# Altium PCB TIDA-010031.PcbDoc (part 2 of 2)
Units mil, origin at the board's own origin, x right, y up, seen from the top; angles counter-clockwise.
Board outline 1982.49 x 1977.57 mil, 2 copper layers (Top Layer, Bottom Layer), stack 62 mil thick; 85 components, 79 nets, 332 pads, 189 vias.
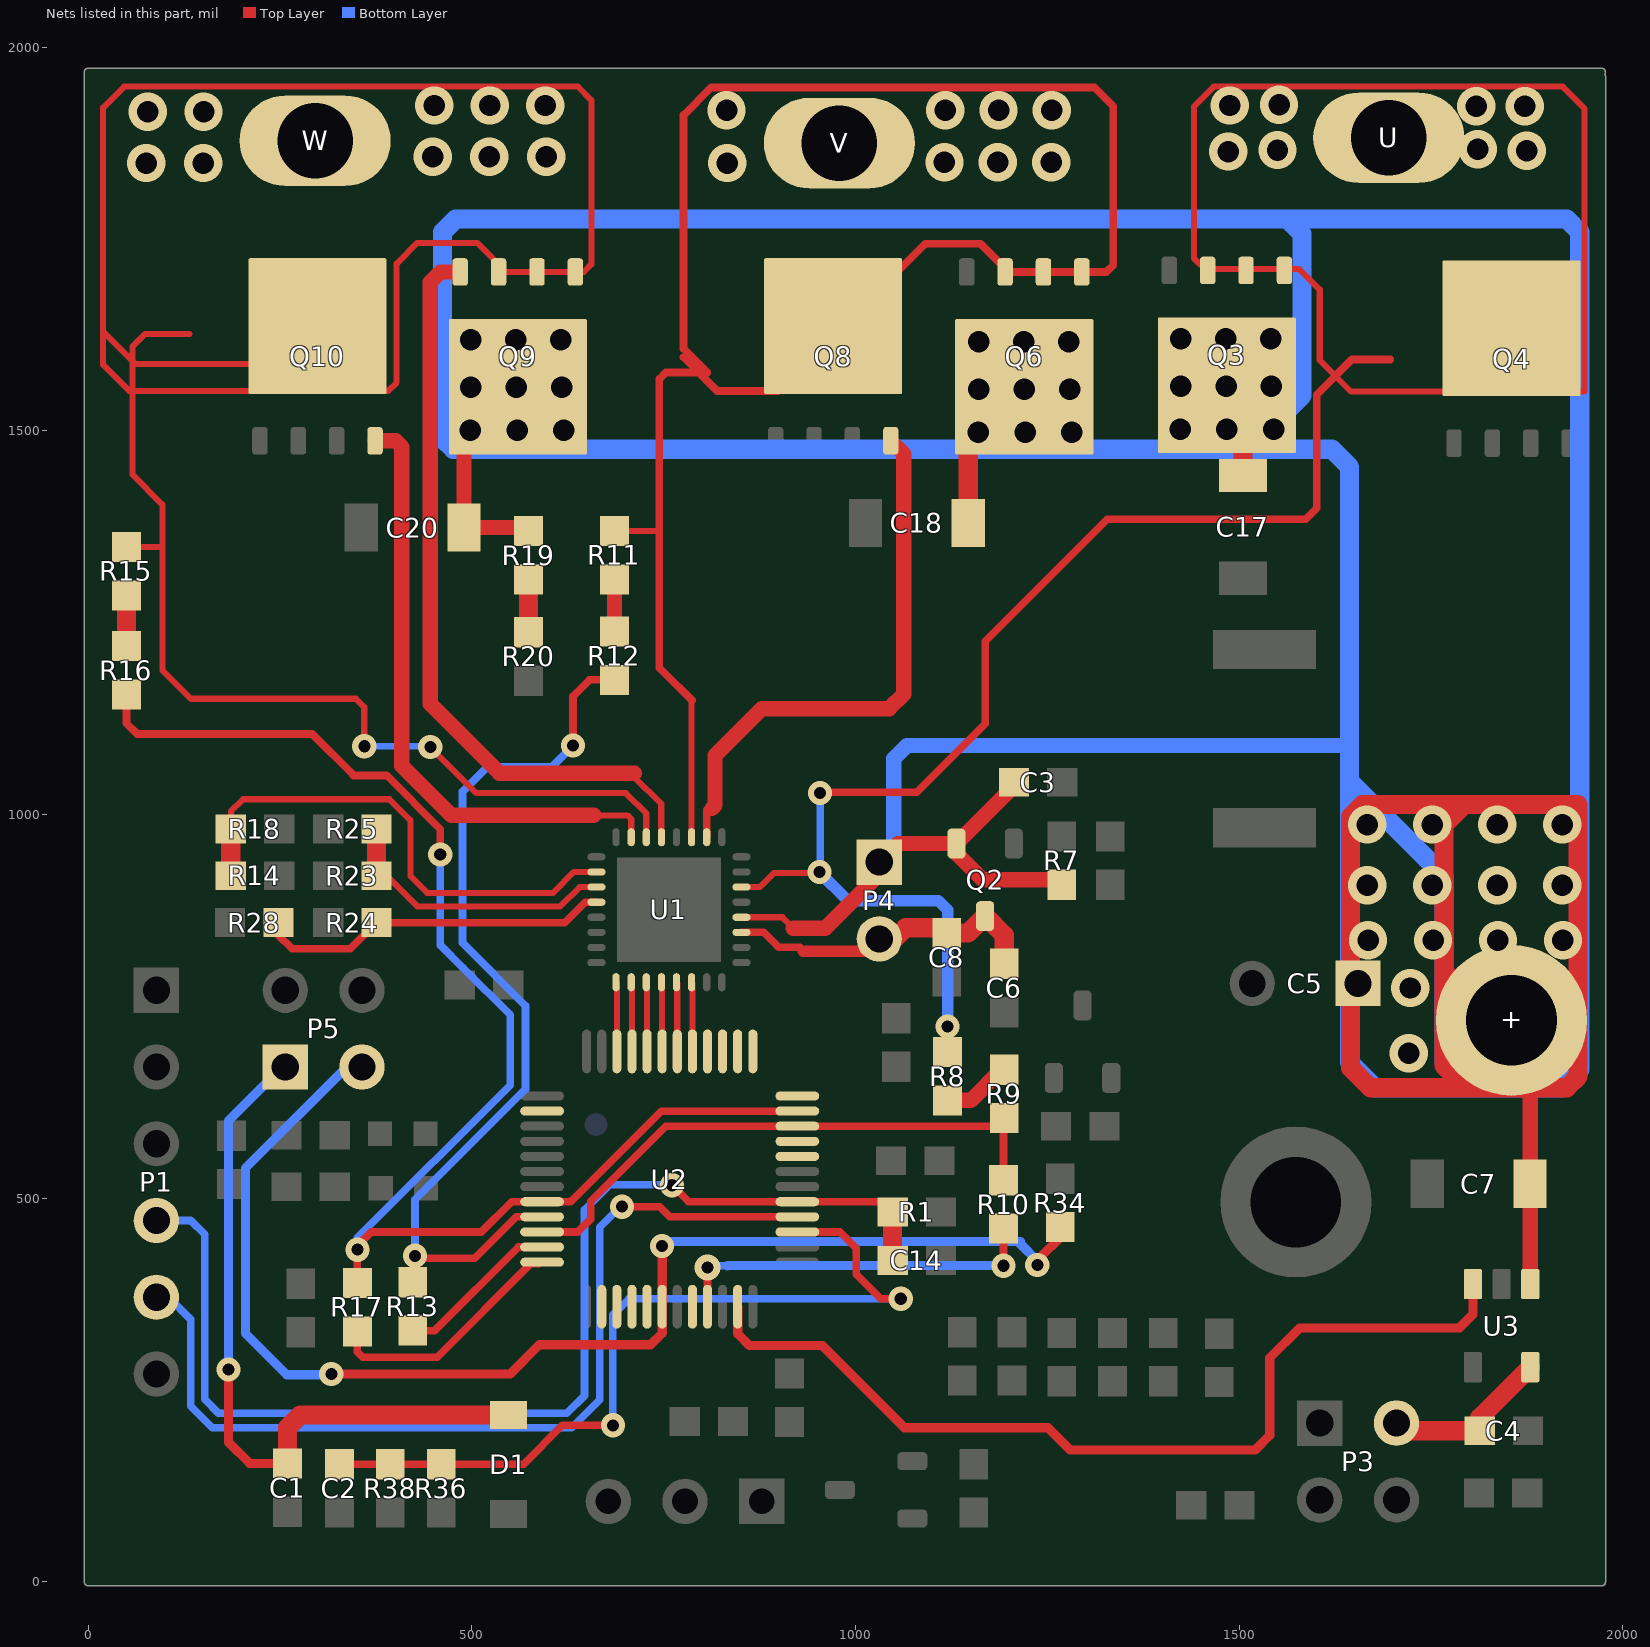
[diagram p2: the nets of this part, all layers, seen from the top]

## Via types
v1: diameter 50, hole 28, Top Layer to Bottom Layer, 132 vias
v2: diameter 31.5, hole 15.75, Top Layer to Bottom Layer, 51 vias
v3: diameter 19.68, hole 7.87, Top Layer to Bottom Layer, 5 vias
v4: diameter 34, hole 16, Top Layer to Bottom Layer, 1 vias

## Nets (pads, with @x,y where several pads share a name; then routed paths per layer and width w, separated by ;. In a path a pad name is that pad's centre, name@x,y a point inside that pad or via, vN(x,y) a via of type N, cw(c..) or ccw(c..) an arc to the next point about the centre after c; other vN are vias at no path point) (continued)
NetQ8_4: Q8.4 U1.10 | length 722.5
  Top Layer w10: U1.10@806.21,970.49 806.21,986.21 806.21,1006.21
  Top Layer w20: 813,1008 817,1012 817,1077 878,1138 1044,1138 1063,1157 1063,1469.96 Q8.4@1046,1486.96
NetQ9_4: Q9.4 U1.13 | length 990.7
  Top Layer w8: 712,1048.93 747,1013.93 747,1011 747,970.65 U1.13@747.16,970.49
  Top Layer w20: Q9.4@485,1707.04 459.04,1707.04 446,1694 446,1293 446,1144 536,1054 712,1054
NetQ10_4: Q10.4 U1.15 | length 839
  Top Layer w8: 625,999 703,999 707.79,994.21 U1.15@707.79,970.49
  Top Layer w20: Q10.4@374,1486.96 401.04,1486.96 409,1479 409,1063.53 473.53,999 625,999 659,999
NetR8_2: R8.2 R9.1 | length 90.6
  Top Layer w20: R8.2@1120,627.5 1150.33,627.5 1190.32,667.5 R9.1@1194,667.5
NetR11_2: R11.2 R12.1 | length 68
  Top Layer w20: R12.1@686,1238.5 R11.2@686,1306.5
NetR14_1: R14.1 R18.2 U1.18 | length 732.2
  Top Layer w8: R14.1@186.06,920.3 186.06,1004.05 202,1020 392.7,1020 420,992.7 420,920 442,898 606,898 633.21,925.21 U1.18@662.51,925.21
  Top Layer w25: R14.1@186.06,920.3 R18.2@186.06,981.3
NetR15_2: R15.2 R16.1 | length 66
  Top Layer w25: R16.1@50,1219.5 R15.2@50,1285.5
NetR19_2: R19.2 R20.1 | length 69
  Top Layer w25: R20.1@574,1237.5 R19.2@574,1306.5
NetR23_1: R23.1 R25.2 U1.19 | length 374.7
  Top Layer w8: R23.1@376.05,920.3 389.23,920.3 429.53,880 615,880 640.53,905.53 U1.19@662.51,905.53
  Top Layer w25: R23.1@376.05,920.3 R25.2@376.05,981.3
NetR24_1: R24.1 R28.2 U1.20 | length 463.7
  Top Layer w10: R28.2@248.05,859.3 248.05,842.95 266,825 341.75,825 R24.1@376.05,859.3 376.35,859 621,859 647.84,885.84 U1.20@662.51,885.84
ON_OFF: C1.1 D1.1 P5.1 | length 951.7
  Top Layer w12: v2(183,277) 183,182 210.5,154.5 C1.1@260,154.5
  Top Layer w25: C1.1@260,154.5 260,201 276.47,217.47 D1.1@548,217.47
  Bottom Layer w12: v2(183,277) 183,601 253,671 P5.1@257,671
P1.0: C2.1 R36.2 R38.2 U2.3 | length 1095.3
  Top Layer w10: C2.1@327.65,153.5 567.5,153.5 618.12,204.12 v2(683.88,204.12) ; U2.3@924.34,456.1 979.65,456.1 1001,434.75 1001,401 1033,369 v2(1059,369)
  Bottom Layer w10: v2(683.88,204.12) 683.88,347.88 705,369 v2(1059,369)
P1.4: R9.2 R10.1 U2.10 U2.34 | length 740
  Top Layer w10: U2.34@591.66,456.1 638.1,456.1 655,473 655,496 752.9,593.9 U2.10@924.34,593.9 1189.1,593.9 1193,590 R10.1@1193,523.5
P1.5: R12.2 R13.1 U2.33 | length 1238.7
  Top Layer w10: R13.1@423,390.5 v2@423,422 ; v2@429,428 v2@434,423 ; v2@433.5,432.5 v2@423,422 ; U2.33@591.66,475.79 557.79,475.79 504,422 v2@423,422 ; v2(632,1090) 632,1154 653.5,1175.5 R12.2@686,1175.5
  Bottom Layer w10: v2(426,425) 426,498 570,642 570,751 488,833 488,1030 520,1062 604,1062 v2(632,1090)
P1.6: R16.2 R17.1 U2.11 U2.32 | length 1884.7
  Top Layer w10: R16.2@50,1156.5 50,1119 64,1105 292,1105 346,1051 389,1051 459,981 v2(459,948) ; R17.1@351,389.5 351,438 369,456 512.46,456 551.93,495.47 U2.32@591.66,495.47 629.02,495.47 747.13,613.58 U2.11@924.34,613.58
  Bottom Layer w10: v2(351,433) 351,448.46 550,647.46 550,739 489,800 ; v2(459,948) 459,830 489,800 ; 502,787 489,800
P2.6: U2.9
P2.7: U2.8
P3.0: U2.47 U3.3 | length 1227.8
  Top Layer w12: U2.47@846.58,358.66 846.58,323.42 862,308 957,308 1064,201 1251,201 1280,172 1521,172 1540,191 1540,292 1579,331 1787,331 1804.6,348.6 U3.3@1804.6,388.13
P3.2: R10.2 U2.45 | length 493.9
  Top Layer w10: U2.45@807.21,358.66 v4(807.21,409.79) v4@807.21,411.79 ; v2(1193,412) R10.2@1193,460.5
  Bottom Layer w10: v4(807.21,409.79) 809.43,412 833,412
  Bottom Layer w12: 833,412 1193,412.25 v2@1193.25,412.25 ; v2@1189.25,408.25 v2(1193,412)
P3.3: U2.44
P3.4: U2.38
P3.6: R17.2 U2.36 | length 316.3
  Top Layer w10: R17.2@351,326.5 351,300 358,293 455,293 577,415 U2.36@587.32,415
P3.7: R13.2 U2.35 | length 213.8
  Top Layer w10: R13.2@423,327.5 451.5,327.5 560.42,436.42 U2.35@591.66,436.42
P4.0: U2.26
P4.4: U2.15
P4.5: U2.14
P4.6: U2.13
P4.7: U2.12
P5.1: P5.3 R34.1 U2.42 | length 1689.9
  Top Layer w12: v2(317,271) 550,271 588,309 733,309 748.16,324.16 U2.42@748.16,358.66 748.16,437.84 v2(748,438) ; v2(1237,413) 1237,419 1272,454 R34.1@1272,457.5
  Bottom Layer w12: v2(317,271) 316,270 259,270 205,324 205,539 337,671 P5.3@357,671 ; v2(748,438) v2@751.75,441.75 ; v2@752.75,443.75 1214.76,443.75 ; 1213.76,441.75 1239,416.51 1239,415 v2(1237,413)
P5.2: U2.41
P5.3: U2.40
P5.4: U2.39
P6.0: U1.25 U2.22 | length 89.2
  Top Layer w8: U2.22@689.1,691.34 U1.25@689.1,780.51
P6.1: U1.26 U2.21 | length 89.2
  Top Layer w8: U2.21@708.79,691.34 U1.26@708.79,780.51
P6.2: U1.27 U2.20 | length 89.2
  Top Layer w8: U2.20@728.47,691.34 U1.27@728.47,780.51
P6.3: U1.28 U2.19 | length 89.2
  Top Layer w8: U2.19@748.16,691.34 U1.28@748.16,780.51
P6.4: U1.29 U2.18 | length 89.2
  Top Layer w8: U2.18@767.84,691.34 U1.29@767.84,780.51
P6.5: U1.30 U2.17 | length 89.2
  Top Layer w8: U2.17@787.53,691.34 U1.30@787.53,780.51
P6.6: U2.16
R\S\T\: C14.1 P1.4 R1.1 U2.5 | length 1513.3
  Top Layer w10: v2(761,517) 782.53,495.47 U2.5@924.34,495.47 R1.1@1035.03,495.47
  Top Layer w25: C14.1@1048.5,419 R1.1@1048.5,482
  Bottom Layer w10: P1.4@89,471 134,471 152,453 152,238 170,220 624,220 647,243 647,485 679.75,517.75 760.25,517.75 v2(761,517)
SBWTCK: P1.5 U2.4 | length 1229
  Top Layer w10: v2(696,489) 745,489 758.21,475.79 U2.4@924.34,475.79
  Bottom Layer w10: P1.5@89,371 105,371 134,342 134,229 162,201 630.46,201 667,237.54 667,462 695,490 v2(696,489)
"U Phase": Q3.1 Q3.2 Q3.3 Q4.5 Q4.6 Q4.7 Q4.8 Q4.9@1855,1633.57 R8.1 U1.6 U.1 | length 3444.6
  Top Layer w8: U1.6@851.49,905.53 875.53,905.53 894,924 952,924 v2(953,925) ; Q3.3@1459,1709.04 1456.96,1709.04 1441,1725 1441,1922.54 1467,1948.54 1921.69,1948.54 1950.22,1920 1950.22,1551.22 1645.78,1551.22 1605,1592 1605,1684 1578,1711 Q3.3@1461,1711
  Top Layer w10: v2(954,1028) 955,1029 1079.64,1029 1169,1118.36 1169,1226 1328,1385 1587,1385 1601,1399 1601,1547 1647.09,1593.09 1697,1593.09 ; R8.1@1120,690.5 v2(1120,724)
  Bottom Layer w10: v2(953,925) 954,926 v2(954,1028)
  Bottom Layer w15: v2(953,925) 990,888 1108,888 1120,876 v2(1120,724)
  other v1: 1486,1864 1875,1865 1550,1866 1811,1867 1809,1923 1872,1923 1488,1924 1552,1925
"V Phase": Q6.1 Q6.2 Q6.3 Q8.5 Q8.6 Q8.7 Q8.8 Q8.9@971,1636.57 R11.1 U1.11 V.1 | length 2556.7
  Top Layer w8: R11.1@686,1369.5 744.02,1369.5 ; U1.11@787,970.96 U1.11@786.53,970.49 786.53,1148.53 787,1149
  Top Layer w10: 776,1596 820,1552 899,1552 1091,1744 1163,1744 1199.96,1707.04 1327.04,1707.04 1336,1716 1336,1923 1311.46,1947.54 812,1947.54 776,1911.54 776,1607.09 807,1576.09 753.09,1576.09 744.53,1567.53 744.53,1191.47 751,1185 787,1149
  other v1: 833,1849 1116,1850 1185.5,1850 1255,1850 832,1918 1117,1918 1186.5,1918 1256,1918
VDriver: C6.1 C8.1 P4.2 Q2.3 U1.3 | length 443.4
  Top Layer w10: U1.3@851.49,846.47 880.53,846.47 898.5,828.5 ; 932,822 927,827 900,827 ; P4.2@1041.5,828.5 P4.2@1050,837 ; 898.5,828.5 900,827 ; 898.5,828.5 900,827 ; 898.5,828.5 900,827
  Top Layer w15: 932,822 1035,822 P4.2@1050,837
  Top Layer w25: P4.2@1050,837 1065.5,852.5 C8.1@1124,852.5 ; C8.1@1119,845.5 1146.74,845.5 Q2.3@1169,867.76 1194,842.76 C6.1@1194,805.5
VLDO: C4.1 P3.2 U3.5 | length 208.7
  Top Layer w25: P3.2@1715,197 C4.1@1813.5,197 1813.5,213.97 U3.5@1879.4,279.87
VM: +.1 C3.1 C5.1 C7.1 C17.1 C18.1 C20.1 P4.1 Q2.2 Q3.5 Q3.6 Q3.7 Q3.8 Q3.9@1484,1559.43 Q6.5 Q6.6 Q6.7 Q6.8 Q6.9@1220,1557.43 Q9.5 Q9.6 Q9.7 Q9.8 Q9.9@560,1557.43 R7.1 R19.1 U1.4 U3.1 | length 10308.2
  Top Layer w8: U1.4@851.49,866.16 904.84,866.16 919,852
  Top Layer w20: Q9.9@489.93,1482.03 C20.1@489.93,1374 R19.1@569.5,1374 ; 919,852 960.82,852 1034.32,925.5 P4.1@1040.5,925.5 ; P4.1@1031,938 1055.24,962.24 Q2.2@1131.6,962.24 ; C3.1@1206.5,1042 1206.5,1037.15 Q2.2@1131.6,962.24 ; R7.1@1269,908.5 1262.5,915 1166,915 1131.6,949.4 Q2.2@1131.6,962.24 ; +.1@1855,732 1879.4,707.6 U3.1@1879.4,388.13
  Top Layer w25: Q6.5@1145,1486.96 1146.93,1485.03 C18.1@1146.93,1380 ; Q3.9@1484,1559.43 1505,1538.43 C17.1@1505,1441.93 ; 1767,808 1767,673 1796,644 ; +.1@1855,732 1830,732 1767,795 1767,987 1793,1013 1841,1013 ; 1796,644 1927,644 1941.72,658.72 1941.72,1013 1841,1013 ; 1796,644 1671,644 1645,670 1645,997 1661,1013 1841,1013
  Bottom Layer w20: P4.1@1050,937 1050,1073 1067,1090 1643,1090 1644,1089
  Bottom Layer w25: 1907,644 1677,644 1644,677 1644,1043 ; 1512,1476 476,1476 462,1490 462,1759 479,1776 1545,1776 ; 1512,1476 1582,1546 ; 1512,1476 1621,1476 1644,1453 1644,1043 ; 1545,1776 1563,1776 ; 1545,1776 1926.85,1776 1943.85,1759 1943.85,667.85 1920,644 1800,644 1767,677 1767,920 1655,1032 1644,1043 ; 1563,1776 1582,1757 ; 1563,1776 1582,1757 ; 1582,1546 1582,1757 ; 1582,1546 1582,1757
  other v1: 1721,689 1723,774 1668,836 1752.67,836 1837.33,836 1922,836 1667,908 1751.67,908 1836.33,908 1921,908 1667,987 1751.67,987 1836.33,987 1921,987 1160,1498 1221,1498 1282,1498 498,1501 559,1501 620,1501 1423,1502 1484,1502 1545,1502 1161,1554 1220,1554 1279,1554 499,1557 558,1557 617,1557 1424,1558 1483,1558 1542,1558 1161,1616 1219.5,1616 1278,1616 499,1619 557.5,1619 616,1619 1424,1620 1482.5,1620 1541,1620
"W Phase": Q9.1 Q9.2 Q9.3 Q10.5 Q10.6 Q10.7 Q10.8 Q10.9@299,1636.57 R15.1 U1.14 W.1 | length 3702
  Top Layer w8: 19.72,1636 19.72,1586 53.72,1552 391,1552 402,1563 402,1718 429,1745 507,1745 544.96,1707.04 646.04,1707.04 656,1717 656,1931 638.46,1948.54 47,1948.54 19.72,1921.25 19.72,1629.28 62,1587 212,1587 261.57,1636.57 Q10.9@299,1636.57 ; R15.1@50,1348.5 95.5,1348.5 ; 132,1626.09 74.09,1626.09 58,1610 58,1443 97,1404 97,1188 134,1151 349,1151 360,1140 v2(360,1089) ; v2(446,1088) 506,1028 586,1028 701,1028 727.47,1001.53 U1.14@727.47,970.49
  Bottom Layer w8: v2(360,1089) 445,1089 v2(446,1088)
  other v1: 76,1849 150,1849 449,1857 523,1857 597,1857 78,1916 150.5,1916 451,1924 523.5,1924 596,1924
pads on no net: Q3.9@1426.91,1543.88 Q3.9@1426.91,1613.96 Q3.9@1484,1543.88 Q3.9@1484,1577.35 Q3.9@1484,1613.96 Q3.9@1541.09,1543.88 Q3.9@1541.09,1613.96 Q4.9@1797.91,1579.04 Q4.9@1797.91,1649.12 Q4.9@1855,1579.04 Q4.9@1855,1615.65 Q4.9@1855,1649.12 Q4.9@1912.09,1579.04 Q4.9@1912.09,1649.12 Q6.9@1162.91,1541.88 Q6.9@1162.91,1611.96 Q6.9@1220,1541.88 Q6.9@1220,1575.35 Q6.9@1220,1611.96 Q6.9@1277.09,1541.88 Q6.9@1277.09,1611.96 Q8.9@913.91,1582.04 Q8.9@913.91,1652.12 Q8.9@971,1582.04 Q8.9@971,1618.65 Q8.9@971,1652.12 Q8.9@1028.09,1582.04 Q8.9@1028.09,1652.12 Q9.9@502.91,1541.88 Q9.9@502.91,1611.96 Q9.9@560,1541.88 Q9.9@560,1575.35 Q9.9@560,1611.96 Q9.9@617.09,1541.88 Q9.9@617.09,1611.96 Q10.9@241.91,1582.04 Q10.9@241.91,1652.12 Q10.9@299,1582.04 Q10.9@299,1618.65 Q10.9@299,1652.12 Q10.9@356.09,1582.04 Q10.9@356.09,1652.12 U1.21 U3.4

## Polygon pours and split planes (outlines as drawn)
IS on Top Layer "Top Overlay-No Net" (solid, remove dead copper, pour order 1000): 1365,1084 1365,1238 1365,1312 1378,1325 1529,1325 1627,1325 1664,1362 1664,1440 1664,1497 1668,1501 1696,1501 1725,1501 1738,1488 1742,1484 1795,1484 1877.22,1484 1895.24,1465.98 1949.22,1412 1949.22,1382 1949.22,1076.22 1936,1063 1805,1063 1385,1063
IS on Top Layer "Top Overlay-No Net" (solid, remove dead copper, pour order 1001): 774,1194 798,1170 816,1170 1004,1170 1029,1195 1031,1197 1031,1395 1031,1454 998,1487 996,1485 830,1485 787.24,1485 774,1471.76
IS on Top Layer "Top Overlay-No Net" (solid, remove dead copper, pour order 1002): 352,1175 372,1195 372,1213 372,1433 314,1491 312,1493 177,1493 128,1493 116,1481 119,1478 119,1439 119,1202 143.82,1177.18 146,1175 151,1175
VM on Top Layer "Top Overlay-No Net" (solid, remove dead copper, pour order 1003): 1647,996 1647,689 1647,667 1673,641 1674,640 1828,640 1920.72,640 1941.72,661 1947,666.28 1947,992 1947,1002 1931,1018 1928,1015 1664,1015
"U Phase" on Top Layer "Top Overlay-No Net" (solid, remove dead copper, pour order 1004): 1442,1923 1442,1724 1454,1712 1455,1711 1575,1711 1603,1683 1606,1680 1606,1620 1606,1592.22 1647,1551.22 1648.22,1550 1764,1550 1947,1550 1951,1554 1952,1555 1952,1687 1952,1917.54 1921,1948.54 1918.54,1951 1471,1951
"V Phase" on Top Layer "Top Overlay-No Net" (solid, remove dead copper, pour order 1005): 1197,1707 1197.04,1707.04 1321,1707.04 1326.04,1707.04 1336,1717 1337,1718 1337,1922 1337,1923 1312,1948 1311,1949 816,1949 811,1949 777,1915 773,1911 773,1820 773,1589 799,1563 812,1550 852,1550 1056,1550 1059,1553 1062,1556 1062,1608 1062,1713 1087,1738 1093,1744 1156,1744 1163,1744 1197.57,1709.43
"W Phase" on Top Layer "Top Overlay-No Net" (solid, remove dead copper, pour order 1006): 387,1550 403,1566 403,1568 403,1719 404.03,1720.03 429,1745 445,1745 509,1745 525,1729 549,1705 619,1705 642,1705 656,1719 660,1723 660,1901 660,1929 638,1951 635.54,1948.54 54,1948.54 47,1948.54 19.72,1921.25 19,1920.54 19,1605 19,1586.72 53.72,1552 55.72,1550 261,1550
GND on Top Layer "Top Overlay-No Net" (solid, remove dead copper, pour order 1007): 1405,514 1402,517 1402,957 1402,973 1431,1002 1440,1011 1589,1011 1592.94,1011 1598.94,1005 1599,1004.94 1599,867 1599,628 1655,572 1672,555 1747,555 1760,555 1766,549 1768,547 1768,445 1768,416 1734,382 1722,370 1608,370 1548,370 1516,402 1405,513 1405,514
GND on Top Layer "Top Overlay-No Net" (solid, remove dead copper, pour order 1008): 1966.77,417.23 1785.77,417.23 1773.77,405.23 1718.77,350.23 1608.77,350.23 1410.77,350.23 1397.77,337.23 1391.77,331.23 1391.77,291.23 1391.77,256.23 1387.77,252.23 1379.77,244.23 1261.77,244.23 1255.77,244.23 1221.77,278.23 1214.77,285.23 1214.77,362.23 1214.77,368.23 1271.77,425.23 1349.77,503.23 1349.77,580.23 1349.77,1042.23 1337.77,1054.23 1335.77,1056.23 1222.77,1056.23 340.77,1056.23 304.77,1092.23 292.77,1104.23 -0.23,1104.23 -0.23,-2.02 0.48,-2.74 193.77,-2.74 1967.8,-2.74 1970.77,0.23
IS on Bottom Layer "Top Overlay-No Net" (solid, remove dead copper, pour order 1009): 118,1419 118,1421 138,1441 144,1447 237,1447 1569,1447 1601,1415 1601,1287 1601,1142 1584,1125 1583,1124 1383,1124 153,1124 118,1159
VM on Bottom Layer "Top Overlay-No Net" (solid, remove dead copper, pour order 1010): 464.86,1761.86 462,1759 462,1492 463,1492 484,1471 489,1466 663,1466 1619,1466 1640,1445 1640,1351 1640,683 1684,639 1687,636 1911,636 1918,636 1947,665 1951,669 1951,920 1951,1749 1924,1776 1921,1779 1323,1779 483,1779 462,1758
"U Phase" on Bottom Layer "Top Overlay-No Net" (solid, remove dead copper, pour order 1011): 1468,1951 1443,1926 1441,1924 1441,1828 1441,1818 1452,1807 1542,1807 1934,1807 1954,1827 1955,1828 1955,1922 1954,1922 1923,1953 1713,1953 1470,1953 1468,1951
"V Phase" on Bottom Layer "Top Overlay-No Net" (solid, remove dead copper, pour order 1012): 812,1950 776,1914 776,1911.54 776,1827 790,1813 953,1813 1318,1813 1340,1835 1341,1836 1341,1923 1341,1925 1315,1951 1314,1952 1186,1952 814,1952 811,1949
"W Phase" on Bottom Layer "Top Overlay-No Net" (solid, remove dead copper, pour order 1013): 21,1924 46,1949 49,1952 162,1952 635,1952 661,1926 660,1925 660,1840 635,1815 403,1815 39,1815 21,1833
GND on Bottom Layer "Top Overlay-No Net" (solid, remove dead copper, pour order 1014): 1400,978 1400,830 1400,510 1400,507 1447.07,459.93 1543,364 1580,364 1714,364 1742.95,392.95 1763,413 1763,433 1763,553 1755,561 1754,562 1687,562 1669,562 1652,579 1596,635 1596,737 1596,1005 1590,1011 1589,1012 1433,1012
GND on Bottom Layer "Top Overlay-No Net" (solid, remove dead copper, pour order 1015): 1399.11,832.03 1384.46,846.67 1384.46,973.67 1384.46,1040.67 1337.46,1087.67 1332.46,1092.67 1034.46,1092.67 31.46,1092.67 -1.54,1059.67 -1.54,1.67 67.46,1.67 69.46,-0.33 71.46,1.67 681.46,1.67 1967.46,1.67 1970.46,4.67 1968.69,6.45 1968.69,140.67 1968.69,406.45 1959.46,415.67 1958.46,416.67 1908.46,416.67 1785.46,416.67 1760.46,391.67 1721.46,352.67 1681.46,352.67 1534.46,352.67 1520.46,366.67 1385.17,501.97 1385.17,586.67 1385.17,715.37 1400.46,730.67 1404.46,734.67 1404.46,824.67

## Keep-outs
Keep-Out Layer:
  lines w10: 0.72,-0.97 0.72,1967.54 1969.22,1967.54 1969.22,-0.97 0.72,-0.97
  text ".Layer_Name" at -406.54,-1607.49 h60

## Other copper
Top Layer:
  text ".Layer_Name" at -406.54,-1607.49 h60
Bottom Layer:
  text ".Layer_Name" at -406.54,-1607.49 h60

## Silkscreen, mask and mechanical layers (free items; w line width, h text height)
Top Overlay:
  circle w177.17: c1217.53,1221 r4.47
  lines w15: 1452,686 1452,875 ; 1498,640 1498,920 ; 1546,623 1546,940 ; 1593,620 1593,940
  text "3.3" at 13,795 h31.5 r270
  text "G" at 1927.46,731 h60 r90
  text "TX" at 12,689 h31.5 r270
  text "RX" at 12,594 h31.5 r270
  text "RST" at 12,503 h31.5 r270
  text "SCK" at 12,399 h31.5 r270
  text "GND" at 12,297 h31.5 r270
  text "PWM" at 635,17 h31.5
  text "FG" at 752,17 h31.5
  text "GND" at 841,16 h31.5
  text ".Layer_Name" at -406.54,-1607.49 h60
Bottom Overlay:
  region: 358.87,212.68 58.87,212.68 58.87,112.68 358.87,112.68
  text "'TIDA-010031'.PCB_Rev-2" at 1805,9 h108.27
  text ".Layer_Name" at -406.54,-1607.49 h60
Top Paste:
  text ".Layer_Name" at -406.54,-1607.49 h60
Bottom Paste:
  text ".Layer_Name" at -406.54,-1607.49 h60
Top Solder:
  text ".Layer_Name" at -406.54,-1607.49 h60
  text ".Layer_Name" at -406.54,-1607.49 h60
Bottom Solder:
  lines w23.62: 670,944 670,785 674,781 836,781 843,788 843,942
  lines w78.74: 56,1887 604,1887 ; 193,1272 1535,1272 ; 195,1163 1539,1163 ; 199,1375 1547,1375 ; 517,1518 1636,1518 ; 527,1645 1639,1645 ; 549,1743 1639,1743 ; 821,1884 1278,1884 ; 1445,526 1445,926 ; 1480,1890 1563,1890 ; 1516,1890 1908,1890 ; 1555,570 1555,954 ; 1671,851 1671,1378 ; 1779,860 1779,1687 ; 1908,867 1908,1721
  text ".Layer_Name" at -406.54,-1607.49 h60
Drill Guide:
  text ".Layer_Name" at -406.54,-1607.49 h60
M1 Board Outline:
  lines w10: 0,1930 cw(c37.64,1929.85) 38,1967.49 ; 0,1967.54 1972.46,1967.54 1972.46,1962.07 ; 0.72,38 ccw(c38.36,37.64) 38.2,0 ; 0.72,1967.54 0.72,-0.97 1973.18,-0.97 ; 1931,-0.97 ccw(c1931.36,36.67) 1969,36.52 ; 1931.76,1968 cw(c1931.6,1930.36) 1969.24,1930 ; 1969.22,-0.97 1969.22,855.03 ; 1969.24,856 1969.24,1968.5
  text ".Layer_Name" at -406.54,-1607.49 h60
M2 Board Dimensions:
  rectangle: -858.54,-1149 -483.54,-1024
  rectangle: -983.54,-1024 -858.54,-899
  lines w7: -983.54,-1024 16.46,-1024 ; -858.54,-1149 -858.54,-899 ; -733.54,-1149 -733.54,-899 ; -483.54,-1149 -483.54,-899 ; -233.54,-1149 -233.54,-899 ; -983.54,-1149 -983.54,-899 16.46,-899 16.46,-1149 -983.54,-1149
  text ".Layer_Name" at -406.54,-1607.49 h60
M3 3D STEP Top:
  text ".Layer_Name" at -406.54,-1607.49 h60
M4 3D STEP Bottom:
  text ".Layer_Name" at -406.54,-1607.49 h60
M5 Assembly Top:
  lines w10: -1275.54,-1679.17 5324.46,-1679.17 ; -1275.54,-1475.83 5326.46,-1475.83 ; -1275.54,-1272.5 -1275.54,-1882.5 2729.46,-1882.5 5326.46,-1882.5 5326.46,-1272.5 -1275.04,-1272.5 -1275.04,-1882.5 300.46,-1882.5 ; 1189.46,-1882.5 1189.46,-1272.5 ; 2456.46,-1475.83 2456.46,-1272.5 ; 3296.46,-1475.83 3296.46,-1272.5 ; 3918.46,-1889 3918.46,-1686.17
  text "COMPONENTS MARKED 'DNP' SHOULD NOT BE POPULATED." at 169.96,-1067.5 h60
  text "ASSEMBLY VARIANT:" at 169.46,-1183 h60
  text ".VariantName" at 1205.46,-1183 h60
  text "PCB VIEWED FROM TOP SIDE" at -1212.04,-1404.67 h60
  text "BOARD #:" at 1264.46,-1404.67 h60
  text ".PRJ_Number" at 1809.96,-1404.67 h60
  text "REV:" at 2654.46,-1404.67 h60
  text ".PCB_Rev" at 2945.96,-1404.67 h60
  text "SVN REV:" at 3492.46,-1404.67 h60
  text ".VersionControl_RevNumber" at 3998.46,-1404.67 h60
  text "TID #:" at 1264.46,-1608 h60
  text ".TID" at 1809.96,-1608 h60
  text "PLOT NAME =" at -1212.04,-1813.34 h60
  text ".plot_File_Name" at -406.54,-1813.34 h60
  text "GENERATED    :" at 1266.46,-1813.34 h60
  text ".Print_Date" at 2135.96,-1813.34 h60
  text ".Print_Time" at 2864.96,-1813.34 h60
  text "TEXAS INSTRUMENTS" at 4129.46,-1813.34 h60
M6 Assembly Bottom:
  lines w10: -1276.04,-1476.33 5325.96,-1476.33 ; -1274.04,-1679.67 5325.96,-1679.67 ; 131.96,-1889.5 131.96,-1686.67 ; 753.96,-1476.33 753.96,-1273 ; 1593.96,-1476.33 1593.96,-1273 ; 2860.96,-1883 2860.96,-1273 ; 3749.96,-1883 5325.46,-1883 5325.46,-1273 -1276.04,-1273 -1276.04,-1883 1320.96,-1883 5325.96,-1883 5325.96,-1273
  text "COMPONENTS MARKED 'DNP' SHOULD NOT BE POPULATED." at 5118.46,-1067 h60
  text ".VariantName" at 4074.46,-1183 h60
  text "ASSEMBLY VARIANT:" at 5113.46,-1183 h60
  text ".VersionControl_RevNumber" at 51.96,-1405.17 h60
  text "SVN REV:" at 557.96,-1405.17 h60
  text ".PCB_Rev" at 1104.46,-1405.17 h60
  text "REV:" at 1395.96,-1405.17 h60
  text ".PRJ_Number" at 2240.46,-1405.17 h60
  text "BOARD #:" at 2785.96,-1405.17 h60
  text "PCB VIEWED FROM BOTTOM SIDE" at 5262.46,-1405.17 h60
  text ".TID" at 2240.46,-1608.5 h60
  text "TID #:" at 2785.96,-1608.5 h60
  text "TEXAS INSTRUMENTS" at -79.04,-1813.84 h60
  text ".Print_Time" at 1185.46,-1813.84 h60
  text ".Print_Date" at 1914.46,-1813.84 h60
  text "GENERATED    :" at 2783.96,-1813.84 h60
  text ".plot_File_Name" at 4456.96,-1813.84 h60
  text "PLOT NAME =" at 5262.46,-1813.84 h60
M9 Title Sheet:
  drawing of 57 lines, arcs and shapes, not listed
  text "1" at -243.7,7287.5 h70
  text "2" at 2251.96,7287.5 h70
  text "3" at 4741.31,7287.5 h70
  text "4" at 7247.98,7287.5 h70
  text "5" at 9746.96,7287.5 h70
  text "6" at 12251.96,7287.5 h70
  text "A" at -1400.04,6144.5 h70
  text "A" at 13399.96,6144.5 h70
  text "B" at -1400.04,3764.5 h70
  text "B" at 13399.96,3764.5 h70
  text "C" at -1400.04,1389.5 h70
  text "C" at 13399.96,1389.5 h70
  text "PROJECT TITLE:" at 10359.96,-471.5 h45
  text "100K RPM Motor Driver Module" at 10409.96,-604.83 h70
  text "DESIGNED FOR:" at 10359.96,-772.5 h45
  text "Public Release" at 10409.96,-912.5 h70
  text "D" at -1400.04,-980.5 h70
  text "D" at 13399.96,-980.5 h70
  text "FILE NAME:" at 10359.96,-1072.5 h45
  text "TIDA-010031.PcbDoc" at 10409.96,-1192.5 h70
  text "Texas Instruments (TI) and/or its licensors do not warrant the accuracy or completeness of this specification" at 5390.46,-1354.34 h45
  text "ENGINEER:" at 10359.96,-1362.5 h45
  text "LAYOUT BY:" at 11864.96,-1362.5 h45
  text "or any information contained therein. TI and/or its licensors do not warrant that this design will meet" at 5345.48,-1467 h45
  text "Hawken Li" at 10409.96,-1517.49 h70
  text "Hawken Li" at 11915.46,-1517.49 h70
  text "the specifications, will be suitable for your application or fit for any particular purpose, or will operate in" at 5345.48,-1579.67 h45
  text ".Layer_Name" at -406.54,-1607.49 h60
  text "ALTIUM DESIGNER VERSION:" at 11864.96,-1672.5 h45
  text "an implementation. TI and/or its licensors do not warrant that the design is production worthy. You should" at 5345.48,-1692.33 h45
  text "completely validate and test your design implementation to confirm the system functionality for your application." at 5390.46,-1805 h45
  text "Scale:1.00" at 10409.96,-1805.83 h70
  text "17.1.9 (Build 472)" at 11915.46,-1805.83 h70
  text "1" at -243.7,-2012.5 h70
  text "2" at 2251.96,-2012.5 h70
  text "3" at 4741.31,-2012.5 h70
  text "4" at 7247.98,-2012.5 h70
  text "5" at 9746.96,-2012.5 h70
  text "6" at 12251.96,-2012.5 h70
M10 Fab Notes:
  drawing of 189 lines, arcs and shapes, not listed
  text "DESIGN INFORMATION" at 11398.48,5607.17 h60
  text "MIN. TRACK WIDTH:" at 10753.92,5475.05 h60
  text "8" at 11850.17,5475.05 h60
  text "MIL" at 12004.92,5475.05 h60
  text "MIN. CLEARANCE:" at 10753.92,5350.92 h60
  text "0.2" at 11790.17,5350.93 h60
  text "mm" at 12004.92,5350.92 h60
  text "MIN. VIA PAD SIZE:" at 10753.92,5226.8 h60
  text "24" at 11820.18,5226.8 h60
  text "MIL" at 12004.92,5226.8 h60
  text "0.05mm (2MIL)" at 11448.92,5096.9 h60
  text "MINIMUM ANNULAR RING" at 10424.69,5088.67 h60
  text "EXTERNAL" at 12156.92,5088.67 h60
  text "PER" at 10624.69,4978.55 h60
  text "IPC-D-275 CLASS 2 LEVEL C" at 10844.69,4978.54 h60
  text "MIL, HOLES" at 12332.92,4878.07 h60
  text "+/-" at 11940.46,4869.48 h60
  text "+/-" at 12794.46,4869.48 h60
  text "REGISTRATION TOLERANCES:" at 10424.69,4868.42 h60
  text "METAL" at 11624.46,4868.42 h60
  text "5" at 12200.67,4868.42 h60
  text "3" at 13033.67,4868.42 h60
  text "MIL" at 13149.92,4868.42 h60
  text "HOLE SIZE TOLERANCE (UNLESS OTHERWISE SPECIFIED):" at 10424.69,4770.1 h60
  text "+/-" at 12794.46,4767.23 h60
  text "3" at 13033.67,4766.17 h60
  text "MIL" at 13149.92,4766.17 h60
  text "MATERIAL:" at 10349.92,4628.52 h60
  text "FR-4 High Tg" at 11336.37,4500 h60
  text "X" at 11191.93,4492.01 h60
  text "FR-408" at 10770.93,4487.49 h60
  text "OTHER" at 12258.92,4487.49 h60
  text "62 MIL (1.6mm) +/-10%" at 11091.03,4344.46 h60
  text "X" at 10970.93,4342.01 h60
  text "THICKNESS:" at 10424.69,4336.24 h60
  text "OTHER" at 12375.92,4336.24 h60
  text "TOLERANCE:" at 10424.69,4197.92 h60
  text "X" at 11272.93,4197.92 h60
  text "ANSI IPC-6012 TYPE 3 CLASS 2" at 11450.94,4197.92 h60
  text "OTHER +/-" at 11450.92,4053.73 h60
  text "BOW & TWIST:" at 10424.69,3908.54 h60
  text "X" at 11272.93,3908.54 h60
  text "ANSI IPC-6012 TYPE 3 CLASS 2" at 11450.94,3908.54 h60
  text "OTHER +/-" at 11450.92,3761.85 h60
  text "DRILLING:" at 10349.92,3631.23 h60
  text "NC_DRILL FILES" at 12110.92,3526.04 h60
  text "REFERENCE:" at 10424.69,3522.1 h60
  text "X" at 11081.93,3522.01 h60
  text "AS SHOWN" at 11259.92,3522.1 h60
  text "X" at 11982.93,3522.1 h60
  text "OTHER" at 12408.92,3379.85 h60
  text "PTH COPPER THICKNESS:" at 10424.37,3376.32 h60
  text "X" at 11563.61,3376.32 h60
  text "20-30 um" at 11691.6,3376.32 h60
  text "BOARD FINISH:" at 10349.92,3228.73 h60
  text "SILKSCREEN:" at 10505.15,3118.6 h60
  text "X" at 11462.93,3118.6 h60
  text "TOP" at 11579.92,3118.6 h60
  text "X" at 11972.93,3118.6 h60
  text "BOTTOM" at 12090.92,3118.6 h60
  text "SILKSCREEN COLOR:" at 10505.15,2963.41 h60
  text "X" at 11461.93,2963.41 h60
  text "WHITE" at 11579.92,2963.41 h60
  text "OTHER" at 12090.92,2963.41 h60
  text "X" at 11592.93,2819.96 h60
  text "GREEN" at 11710.92,2819.96 h60
  text "OTHER" at 12328.92,2819.96 h60
  text "SOLDER RESIST COLOR:" at 10505.15,2813.1 h60
  text "X" at 11592.93,2665.71 h60
  text "MATTE" at 11710.92,2665.71 h60
  text "SEMI-GLOSS" at 12328.46,2665.07 h60
  text "IMMERSION GOLD (ENIG)" at 11410.92,2492.94 h60
  text "ENEPIG" at 12748.46,2485.72 h60
  text "SURFACE FINISH:" at 10349.92,2484.72 h60
  text "X" at 11232.93,2484.72 h60
  text "IMM. TIN/SILVER OR EQUIV" at 10679.46,2347.4 h60
  text "OTHER" at 12110.92,2343.47 h60
  text "ARRAY/PANEL:" at 10349.92,2188.09 h60
  text "CUT AND TRIM PER M1 BOARD OUTLINE" at 11410.92,2179.87 h60
  text "N.C. ROUTE" at 11410.92,2043.9 h60
  text "X" at 12098.93,2043.9 h60
  text "V. SCORE" at 12276.92,2043.9 h60
  text "CERTIFICATION:" at 10349.92,1914.77 h60
  text "MATERIALS AND WORKMANSHIP FOR ALL PCBS" at 11074.92,1914.77 h60
  text "TO MEET OR EXCEED THE REQUIREMENTS OF:" at 11074.92,1820.71 h60
  text "X" at 10712.43,1692.08 h60
  text "ANSI IPC-A-600F CLASS ->" at 10840.43,1692.08 h60
  text "X" at 12488.43,1692.08 h60
  text "2" at 12598.43,1692.08 h60
  text "1" at 12283.43,1690.58 h60
  text "3" at 12952.43,1690.58 h60
  text "X" at 11524.43,1544.39 h60
  text "RoHS" at 11652.43,1544.39 h60
  text "OTHER" at 12296.83,1544.39 h60
  text "PER ORDER" at 12693.89,1544.39 h60
  text "ALL BOARDS MUST MEET OR EXCEED UL94-V0 REQUIREMENTS." at 10377.46,1390.57 h60
  text "PCB MUST BEAR THE UL94V-0 UL REGISTERED MATERIAL ID NUMBER" at 10377.46,1274.5 h60
  text "ADDITIONAL REQUIREMENTS:" at 10349.92,1105.08 h60
  text "MICROSECTION:" at 10424.69,997.95 h60
  text "YES" at 11330.43,997.95 h60
  text "REQUIRED" at 12191.92,853.62 h60
  text "BARE BOARD ELEC. TEST:" at 10424.69,850.76 h60
  text "NONE" at 11730.43,850.76 h60
  text "X" at 12073.93,850.76 h60
  text "PER ORDER" at 12783.92,850.76 h60
  text "XX MIL VIAS REQUIRE NON-CONDUCTIVE FILL AND PLANARIZE" at 10592.84,645.82 h59
  text "XX MIL VIAS REQUIRE CONDUCTIVE FILL AND PLANARIZE" at 10600.84,541.84 h60
  text "OUTER XX MIL TRACES REQUIRE 50 OHM SINGLE-ENDED IMPEDANCE" at 10599.86,378.46 h58
  text "LAYER 2 & 3 (INNER LAYERS) XX MIL WIDE, XX MIL SPACE / TRACES REQUIRE 100 OHM DIFFERENTIAL IMPEDANCE" at 10591.86,142.74 h60
  text ".Layer_Name" at -406.54,-1607.49 h60
M11 Gerber Information:
  lines w10: -1275.54,-1679.17 5324.46,-1679.17 ; -1275.54,-1475.83 5326.46,-1475.83 ; -1275.54,-1272.5 -1275.54,-1882.5 2729.46,-1882.5 5326.46,-1882.5 5326.46,-1272.5 -1275.04,-1272.5 -1275.04,-1882.5 300.46,-1882.5 ; 1189.46,-1882.5 1189.46,-1272.5 ; 2456.46,-1475.83 2456.46,-1272.5 ; 3296.46,-1475.83 3296.46,-1272.5 ; 3918.46,-1889 3918.46,-1686.17
  text "ALL ARTWORK VIEWED FROM TOP SIDE" at -1212.04,-1404.67 h60
  text "BOARD #:" at 1264.46,-1404.67 h60
  text ".PRJ_Number" at 1809.96,-1404.67 h60
  text "REV:" at 2654.46,-1404.67 h60
  text ".PCB_Rev" at 2945.96,-1404.67 h60
  text "SVN REV:" at 3492.46,-1404.67 h60
  text ".VersionControl_RevNumber" at 3998.46,-1404.67 h60
  text "LAYER NAME =" at -1212.04,-1607.49 h60
  text "TID #:" at 1264.46,-1608 h60
  text ".TID" at 1809.96,-1608 h60
  text "PLOT NAME =" at -1212.04,-1813.34 h60
  text ".plot_File_Name" at -406.54,-1813.34 h60
  text "GENERATED    :" at 1266.46,-1813.34 h60
  text ".Print_Date" at 2135.96,-1813.34 h60
  text ".Print_Time" at 2864.96,-1813.34 h60
  text "TEXAS INSTRUMENTS" at 4129.46,-1813.34 h60
M12 Stackup:
  drawing of 191 lines, arcs and shapes, not listed
  text "Layer" at 8814.31,7081 h60
  text "Name" at 9224.22,7081 h60
  text "Material" at 10153.96,7081 h60
  text "Thickness" at 11013.73,7081 h60
  text "Constant" at 11663.57,7081 h60
  text "Board Layer Stack" at 12233.43,7081 h60
  text "1" at 8814.31,6961 h60
  text "Top Overlay" at 9224.22,6961 h60
  text "2" at 8814.31,6841 h60
  text "Top Solder" at 9224.22,6841 h60
  text "Solder Resist" at 10153.96,6841 h60
  text "0.40mil" at 11013.73,6841 h60
  text "3.5" at 11663.57,6841 h60
  text "3" at 8814.31,6721 h60
  text "Top Layer" at 9224.22,6721 h60
  text "Copper" at 10153.96,6721 h60
  text "1.40mil" at 11013.73,6721 h60
  text "4" at 8814.31,6601 h60
  text "Dielectric1" at 9224.22,6601 h60
  text "FR-4" at 10153.96,6601 h60
  text "59.20mil" at 11013.73,6601 h60
  text "4.8" at 11663.57,6601 h60
  text "5" at 8814.31,6481 h60
  text "Bottom Layer" at 9224.22,6481 h60
  text "Copper" at 10153.96,6481 h60
  text "1.40mil" at 11013.73,6481 h60
  text "6" at 8814.31,6361 h60
  text "Bottom Solder" at 9224.22,6361 h60
  text "Solder Resist" at 10153.96,6361 h60
  text "0.40mil" at 11013.73,6361 h60
  text "3.5" at 11663.57,6361 h60
  text "7" at 8814.31,6241 h60
  text "Bottom Overlay" at 9224.22,6241 h60
  text ".Layer_Name" at -406.54,-1607.49 h60
M13 Component Bodies Top:
  text ".Layer_Name" at -406.54,-1607.49 h60
M14 Component Bodies Bottom:
  text ".Layer_Name" at -406.54,-1607.49 h60
M15 Courtyards Top:
  text ".Layer_Name" at -406.54,-1607.49 h60
M16 Courtyards Bottom:
  text ".Layer_Name" at -406.54,-1607.49 h60
  text ".Layer_Name" at -406.54,-1607.49 h60
  text ".Layer_Name" at -406.54,-1607.49 h60
  text ".Layer_Name" at -406.54,-1607.49 h60
Drill Drawing:
  circle w10: c4365.36,1956.05 r22.14
  circle w10: c4365.36,1956.05 r13.28
  lines w10: 4343.22,2033.53 4343.22,2077.81 4387.5,2077.81 4387.5,2033.53 4343.22,2033.53 ; 4343.22,2133.15 4343.22,2177.43 4387.5,2177.43 4387.5,2133.15 4343.22,2133.15 ; 4343.22,2232.77 4354.29,2254.91 4343.22,2277.05 4365.36,2265.98 4387.5,2277.05 4376.43,2254.91 4387.5,2232.77 4365.36,2243.84 4343.22,2232.77 ; 4343.22,2376.67 4365.36,2332.4 4387.5,2376.67 4343.22,2376.67 ; 4343.22,2454.16 4365.36,2476.3 4387.5,2454.16 4365.36,2432.02 4343.22,2454.16 ; 4343.22,2542.71 4343.22,2564.85 4354.29,2564.85 4354.29,2575.92 4376.43,2575.92 4376.43,2564.85 4387.5,2564.85 4387.5,2542.71 4376.43,2542.71 4376.43,2531.64 4354.29,2531.64 4354.29,2542.71 4343.22,2542.71 ; 4352.08,2042.39 4352.08,2068.95 4378.65,2068.95 4378.65,2042.39 4352.08,2042.39 ; 4352.08,2367.82 4365.36,2341.25 4378.65,2367.82 4352.08,2367.82
  lines w12: 4302.46,1904.02 7415.4,1904.02 ; 4302.46,2601.38 7415.4,2601.38 ; 4618.1,1804.4 4618.1,2701 ; 4935.28,1804.4 4935.28,2701 ; 5557.03,1804.4 5557.03,2701 ; 5801.35,1804.4 5801.35,2701 ; 6161.69,1804.4 6161.69,2701 ; 6871.2,1804.4 6871.2,2701 ; 4302.46,1804.4 4302.46,2701 7415.4,2701 7415.4,1804.4 4302.46,1804.4
  text "Symbol" at 4362.24,2631.26 h72
  text "Quantity" at 4647.99,2631.26 h72
  text "Finished Hole Size" at 4965.17,2631.26 h72
  text "Plated" at 5586.91,2631.26 h72
  text "Hole Type" at 5831.23,2631.26 h72
  text "Drill Layer Pair" at 6191.57,2631.26 h72
  text "Hole Tolerance" at 6901.08,2631.26 h72
  text "5" at 4647.99,2531.64 h60
  text "7.87mil (0.200mm)" at 4965.17,2531.64 h60
  text "PTH" at 5586.91,2531.64 h60
  text "Round" at 5831.23,2531.64 h60
  text "Top Layer - Bottom Layer" at 6191.57,2531.64 h60
  text "31" at 4647.99,2432.02 h60
  text "15.75mil (0.400mm)" at 4965.17,2432.02 h60
  text "PTH" at 5586.91,2432.02 h60
  text "Round" at 5831.23,2432.02 h60
  text "Top Layer - Bottom Layer" at 6191.57,2432.02 h60
  text "252" at 4647.99,2332.4 h60
  text "18.00mil (0.457mm)" at 4965.17,2332.4 h60
  text "PTH" at 5586.91,2332.4 h60
  text "Round" at 5831.23,2332.4 h60
  text "Top Layer - Bottom Layer" at 6191.57,2332.4 h60
  text "2" at 4647.99,2232.77 h60
  text "35.00mil (0.889mm)" at 4965.17,2232.77 h60
  text "PTH" at 5586.91,2232.77 h60
  text "Round" at 5831.23,2232.77 h60
  text "Top Layer - Bottom Layer" at 6191.57,2232.77 h60
  text "20" at 4647.99,2133.15 h60
  text "35.43mil (0.900mm)" at 4965.17,2133.15 h60
  text "PTH" at 5586.91,2133.15 h60
  text "Round" at 5831.23,2133.15 h60
  text "Top Layer - Bottom Layer" at 6191.57,2133.15 h60
  text "2" at 4647.99,2033.53 h60
  text "59.06mil (1.500mm)" at 4965.17,2033.53 h60
  text "PTH" at 5586.91,2033.53 h60
  text "Round" at 5831.23,2033.53 h60
  text "Top Layer - Bottom Layer" at 6191.57,2033.53 h60
  text "2" at 4647.99,1933.91 h60
  text "78.74mil (2.000mm)" at 4965.17,1933.91 h60
  text "PTH" at 5586.91,1933.91 h60
  text "Round" at 5831.23,1933.91 h60
  text "Top Layer - Bottom Layer" at 6191.57,1933.91 h60
  text "314 Total" at 4647.99,1834.29 h60
  text ".Layer_Name" at -406.54,-1607.49 h60

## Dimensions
0.72,-0.97 to 1969.22,-0.97 on M2 Board Dimensions
0.72,-0.97 to 0,1967.54 on M2 Board Dimensions
-983.54,-1149 to 16.46,-1149 on M2 Board Dimensions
